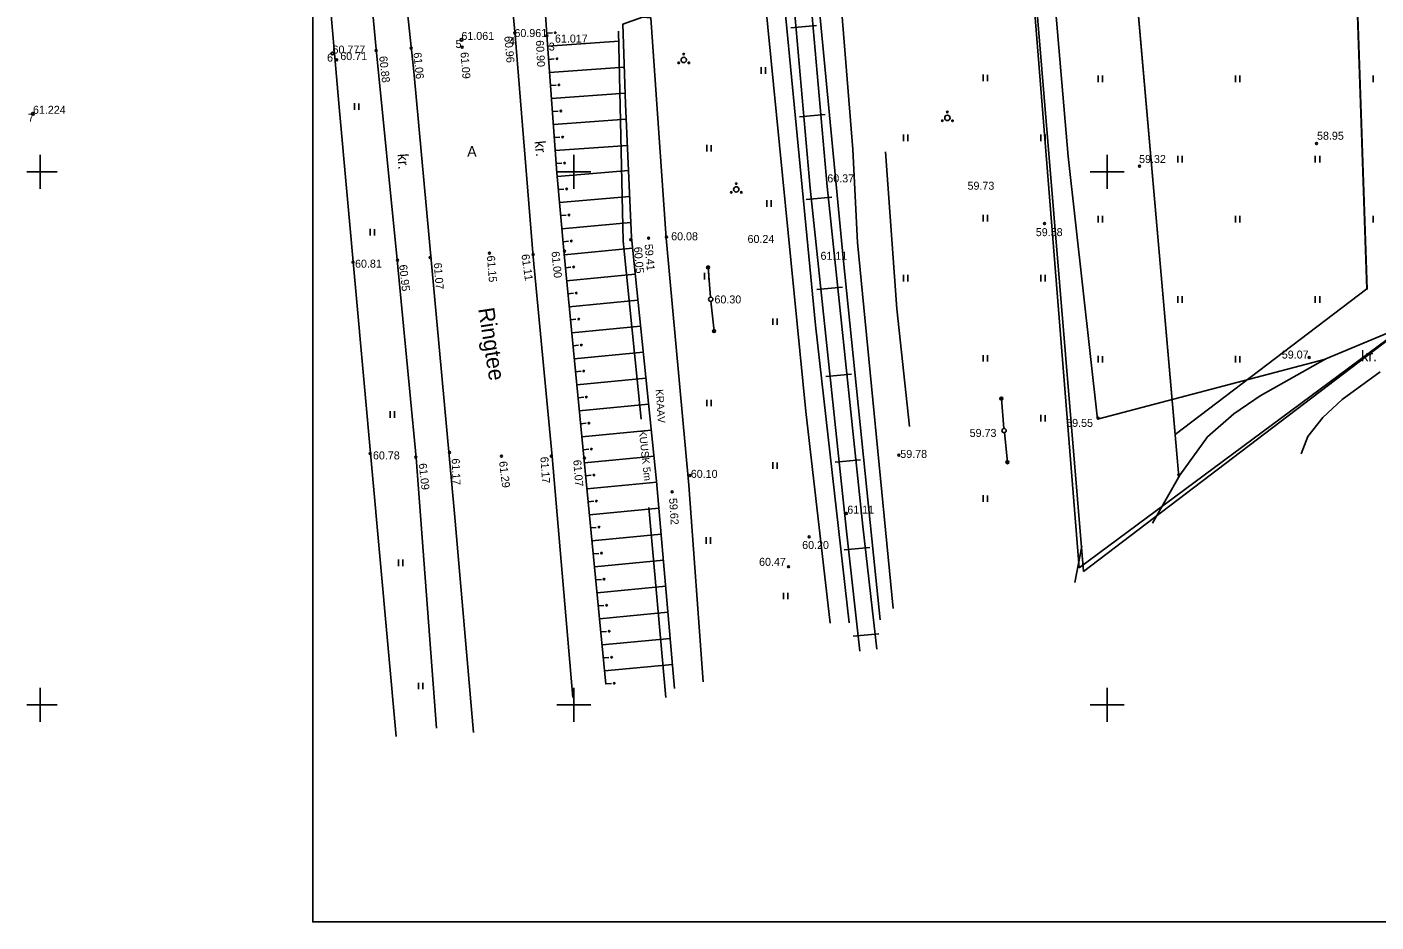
# Model space of a CAD drawing. Extents: x 9156 to 9809, y 2728 to 4000.
# Drawn here: x 9248.8 to 9375.2, y 3329.6 to 3413.6 of the extents above; entities that cross this region are included whole.
import ezdxf

# ---------------------------------------------------------------- set-up
doc = ezdxf.new("R2010")
doc.units = 0
for name, color, linetype in [('Level 1', 7, 'Continuous'), ('Level 11', 7, 'Continuous'), ('Level 54', 7, 'Continuous'), ('Level 58', 7, 'Continuous'), ('Level 6', 7, 'Continuous'), ('Level 63', 7, 'Continuous'), ('Level 7', 7, 'Continuous')]:
    doc.layers.add(name, color=color, linetype=linetype)

# ---------------------------------------------------------------- blocks, each defined once
blk = doc.blocks.new('KKOL')
at = {"layer": 'Level 58'}
for p, q in [((0, 1.59349), (0, -1.5935)), ((-1.5935, 0), (1.59349, 0))]:
    blk.add_line(p, q, dxfattribs=at)

msp = doc.modelspace()

# ---------------------------------------------------------------- linework, layer by layer
at = {"layer": 'Level 1'}
for p, q in [((9347.38, 3362.85), (9317.65, 3734.12)), ((9347.38, 3362.85), (9317.65, 3734.12)), ((9524.24, 3494.13), (9347.38, 3362.85)), ((9524.24, 3494.13), (9347.38, 3362.85)), ((9356.73, 3371.39), (9356.63, 3371.66)), ((9356.63, 3371.66), (9356.73, 3371.53)), ((9356.73, 3371.39), (9356.63, 3371.66)), ((9356.63, 3371.66), (9356.73, 3371.53)), ((9356.73, 3371.39), (9356.63, 3371.66)), ((9356.63, 3371.66), (9356.73, 3371.53)), ((9356.73, 3371.39), (9356.63, 3371.66)), ((9356.63, 3371.66), (9356.73, 3371.53)), ((9356.73, 3371.39), (9356.63, 3371.66)), ((9356.63, 3371.66), (9356.73, 3371.53)), ((9356.73, 3371.39), (9356.63, 3371.66)), ((9356.63, 3371.66), (9356.73, 3371.53)), ((9356.73, 3371.39), (9356.63, 3371.66)), ((9356.63, 3371.66), (9356.73, 3371.53)), ((9356.73, 3371.39), (9356.63, 3371.66)), ((9356.63, 3371.66), (9356.73, 3371.53)), ((9356.89, 3371.7), (9356.73, 3371.39)), ((9356.73, 3371.53), (9356.89, 3371.7)), ((9356.89, 3371.7), (9356.73, 3371.39)), ((9356.73, 3371.53), (9356.89, 3371.7)), ((9356.89, 3371.7), (9356.73, 3371.39)), ((9356.73, 3371.53), (9356.89, 3371.7)), ((9356.89, 3371.7), (9356.73, 3371.39)), ((9356.73, 3371.53), (9356.89, 3371.7)), ((9356.89, 3371.7), (9356.73, 3371.39)), ((9356.73, 3371.53), (9356.89, 3371.7)), ((9356.89, 3371.7), (9356.73, 3371.39)), ((9356.73, 3371.53), (9356.89, 3371.7)), ((9356.89, 3371.7), (9356.73, 3371.39)), ((9356.73, 3371.53), (9356.89, 3371.7)), ((9356.89, 3371.7), (9356.73, 3371.39)), ((9356.73, 3371.53), (9356.89, 3371.7)), ((9347.63, 3364.87), (9346.98, 3361.49)), ((9347.63, 3364.87), (9346.98, 3361.49))]:
    msp.add_line(p, q, dxfattribs=at)
at = {"layer": 'Level 11'}
msp.add_lwpolyline([(9370.59, 3498.94), (9345.6, 3498.32), (9356.38, 3375.35), (9374.34, 3389.03)], close=True, dxfattribs=at)
msp.add_lwpolyline([(9370.59, 3498.94), (9345.6, 3498.32), (9356.38, 3375.35), (9374.34, 3389.03)], close=True, dxfattribs=at)
at = {"layer": 'Level 54'}
for p, q in [((9320.71, 3439.87), (9325.24, 3391.91)), ((9294.51, 3412.82), (9292.27, 3435.4)), ((9283.43, 3424.1), (9285, 3409.41)), ((9346.35, 3401.44), (9344.53, 3422.43)), ((9321.74, 3377.52), (9317.43, 3421.43)), ((9281.48, 3411.48), (9281.03, 3416.19)), ((9322.66, 3385.6), (9319.8, 3415.37)), ((9297.48, 3412.99), (9298.01, 3413.02)), ((9304.2, 3413.18), (9304.64, 3393.5)), ((9320.36, 3413.49), (9322.76, 3413.7)), ((9296.2, 3392.01), (9294.51, 3412.82)), ((9304.22, 3412.24), (9297.57, 3411.76)), ((9283.45, 3391.74), (9281.48, 3411.48)), ((9297.66, 3410.54), (9298.18, 3410.58)), ((9285, 3409.41), (9288.81, 3367.95)), ((9304.73, 3409.82), (9297.74, 3409.32)), ((9317.57, 3409.81), (9317.57, 3409.19)), ((9317.97, 3409.8), (9317.97, 3409.19)), ((9338.37, 3409.11), (9338.37, 3408.49)), ((9338.78, 3409.1), (9338.78, 3408.49)), ((9297.83, 3408.1), (9298.36, 3408.13)), ((9349.15, 3409.02), (9349.15, 3408.4)), ((9349.56, 3409.01), (9349.56, 3408.4)), ((9362.03, 3409.02), (9362.03, 3408.4)), ((9362.44, 3409.01), (9362.44, 3408.4)), ((9374.92, 3409.02), (9374.92, 3408.4)), ((9304.82, 3407.37), (9297.92, 3406.87)), ((9279.46, 3406.42), (9279.46, 3405.8)), ((9279.86, 3406.41), (9279.86, 3405.8)), ((9298.01, 3405.65), (9298.53, 3405.69)), ((9321.16, 3405.14), (9323.56, 3405.36)), ((9304.92, 3404.92), (9298.1, 3404.43)), ((9298.18, 3403.21), (9298.71, 3403.24)), ((9330.9, 3403.49), (9330.9, 3402.87)), ((9331.3, 3403.48), (9331.3, 3402.87)), ((9343.78, 3403.49), (9343.78, 3402.87)), ((9344.18, 3403.48), (9344.18, 3402.87)), ((9250, 3401.59), (9250, 3398.41)), ((9305.03, 3402.47), (9298.27, 3401.98)), ((9312.47, 3402.51), (9312.47, 3401.89)), ((9312.87, 3402.5), (9312.87, 3401.89)), ((9356.63, 3401.49), (9356.63, 3400.87)), ((9357.03, 3401.48), (9357.03, 3400.87)), ((9369.51, 3401.49), (9369.51, 3400.87)), ((9369.92, 3401.48), (9369.92, 3400.87)), ((9250, 3401.25), (9250, 3398.75)), ((9298.36, 3400.76), (9298.88, 3400.8)), ((9300, 3401.25), (9300, 3398.75)), ((9349.08, 3376.81), (9346.35, 3401.44)), ((9350, 3401.25), (9350, 3398.75)), ((9248.75, 3400), (9251.25, 3400)), ((9250, 3400), (9251.59, 3400)), ((9305.13, 3400.13), (9298.45, 3399.54)), ((9298.75, 3400), (9301.25, 3400)), ((9348.75, 3400), (9351.25, 3400)), ((9298.56, 3398.32), (9299.08, 3398.36)), ((9305.24, 3397.68), (9298.67, 3397.1)), ((9318.11, 3397.33), (9318.11, 3396.71)), ((9318.52, 3397.32), (9318.52, 3396.71)), ((9321.8, 3397.38), (9324.2, 3397.6)), ((9298.77, 3395.88), (9299.3, 3395.92)), ((9305.35, 3395.23), (9298.88, 3394.66)), ((9338.37, 3395.96), (9338.37, 3395.34)), ((9338.78, 3395.95), (9338.78, 3395.34)), ((9349.15, 3395.87), (9349.15, 3395.25)), ((9349.56, 3395.86), (9349.56, 3395.25)), ((9362.03, 3395.87), (9362.03, 3395.25)), ((9362.44, 3395.86), (9362.44, 3395.25)), ((9374.92, 3395.87), (9374.92, 3395.25)), ((9280.93, 3394.63), (9280.93, 3394.01)), ((9281.33, 3394.62), (9281.33, 3394.01)), ((9298.99, 3393.44), (9299.51, 3393.48)), ((9305.52, 3392.84), (9299.1, 3392.21)), ((9304.64, 3393.5), (9306.33, 3376.81)), ((9285.24, 3373.17), (9283.45, 3391.74)), ((9297.99, 3373.29), (9296.2, 3392.01)), ((9325.24, 3391.91), (9328.1, 3364.05)), ((9299.22, 3390.99), (9299.74, 3391.05)), ((9305.77, 3390.4), (9299.33, 3389.77)), ((9312.26, 3390.51), (9312.26, 3389.89)), ((9312.82, 3388.24), (9312.59, 3391.03)), ((9312.67, 3390.5), (9312.67, 3389.89)), ((9330.9, 3390.34), (9330.9, 3389.72)), ((9331.3, 3390.33), (9331.3, 3389.72)), ((9343.78, 3390.34), (9343.78, 3389.72)), ((9344.18, 3390.33), (9344.18, 3389.72)), ((9322.79, 3388.96), (9325.19, 3389.18)), ((9386.88, 3389.34), (9370.49, 3382.44)), ((9299.45, 3388.55), (9299.98, 3388.61)), ((9306.02, 3387.96), (9299.57, 3387.34)), ((9312.86, 3387.85), (9313.15, 3385.06)), ((9356.63, 3388.34), (9356.63, 3387.72)), ((9357.03, 3388.33), (9357.03, 3387.72)), ((9369.51, 3388.34), (9369.51, 3387.72)), ((9369.92, 3388.33), (9369.92, 3387.72)), ((9299.69, 3386.12), (9300.21, 3386.17)), ((9306.27, 3385.52), (9299.81, 3384.9)), ((9318.65, 3386.25), (9318.65, 3385.63)), ((9319.06, 3386.24), (9319.06, 3385.63)), ((9325.8, 3357.7), (9322.66, 3385.6)), ((9299.93, 3383.68), (9300.45, 3383.73)), ((9306.52, 3383.09), (9300.05, 3382.46)), ((9338.37, 3382.81), (9338.37, 3382.19)), ((9338.78, 3382.8), (9338.78, 3382.19)), ((9349.15, 3382.72), (9349.15, 3382.1)), ((9349.56, 3382.71), (9349.56, 3382.1)), ((9362.03, 3382.72), (9362.03, 3382.1)), ((9362.44, 3382.71), (9362.44, 3382.1)), ((9300.17, 3381.24), (9300.69, 3381.29)), ((9370.47, 3382.43), (9349.08, 3376.81)), ((9370.49, 3382.44), (9364.33, 3378.97)), ((9306.77, 3380.65), (9300.28, 3380.02)), ((9323.62, 3380.79), (9326.02, 3381.01)), ((9375.6, 3381.22), (9372.04, 3378.63)), ((9300.4, 3378.8), (9300.93, 3378.85)), ((9340.32, 3375.93), (9340.08, 3378.72)), ((9364.33, 3378.97), (9361.87, 3377.28)), ((9282.8, 3377.55), (9282.8, 3376.93)), ((9283.2, 3377.54), (9283.2, 3376.93)), ((9307.02, 3378.21), (9300.52, 3377.58)), ((9312.47, 3378.62), (9312.47, 3378)), ((9312.87, 3378.61), (9312.87, 3378)), ((9324.04, 3357.67), (9321.74, 3377.52)), ((9372.04, 3378.63), (9370.22, 3376.95)), ((9300.64, 3376.36), (9301.16, 3376.41)), ((9343.78, 3377.19), (9343.78, 3376.57)), ((9344.18, 3377.18), (9344.18, 3376.57)), ((9361.87, 3377.28), (9359.4, 3375.14)), ((9370.22, 3376.95), (9368.82, 3375.17)), ((9307.27, 3375.77), (9300.76, 3375.14)), ((9340.36, 3375.53), (9340.65, 3372.75)), ((9359.4, 3375.14), (9356.82, 3371.54)), ((9368.82, 3375.17), (9368.18, 3373.54)), ((9300.88, 3373.92), (9301.4, 3373.97)), ((9287.14, 3347.81), (9285.24, 3373.17)), ((9299.9, 3350.68), (9297.99, 3373.29)), ((9307.53, 3373.33), (9301, 3372.7)), ((9318.65, 3372.75), (9318.65, 3372.13)), ((9319.06, 3372.74), (9319.06, 3372.13)), ((9324.49, 3372.75), (9326.89, 3372.97)), ((9301.11, 3371.48), (9301.64, 3371.53)), ((9356.82, 3371.54), (9354.24, 3367.05)), ((9307.78, 3370.89), (9301.23, 3370.26)), ((9301.35, 3369.04), (9301.87, 3369.09)), ((9338.37, 3369.66), (9338.37, 3369.04)), ((9338.78, 3369.65), (9338.78, 3369.04)), ((9288.81, 3367.95), (9290.59, 3347.42)), ((9307.99, 3368.45), (9301.47, 3367.82)), ((9307.05, 3368.52), (9308.62, 3350.69)), ((9301.59, 3366.6), (9302.11, 3366.65)), ((9308.2, 3366.01), (9301.71, 3365.38)), ((9312.4, 3365.73), (9312.4, 3365.11)), ((9312.81, 3365.72), (9312.81, 3365.11)), ((9283.58, 3363.63), (9283.58, 3363.01)), ((9283.99, 3363.62), (9283.99, 3363.01)), ((9301.83, 3364.16), (9302.35, 3364.21)), ((9308.41, 3363.57), (9301.94, 3362.94)), ((9325.36, 3364.54), (9327.76, 3364.75)), ((9328.1, 3364.05), (9328.72, 3357.98)), ((9302.06, 3361.72), (9302.59, 3361.77)), ((9308.62, 3361.13), (9302.18, 3360.5)), ((9319.67, 3360.52), (9319.67, 3359.9)), ((9320.08, 3360.5), (9320.08, 3359.9)), ((9302.3, 3359.28), (9302.82, 3359.33)), ((9308.83, 3358.68), (9302.42, 3358.06)), ((9302.54, 3356.84), (9303.06, 3356.89)), ((9309.04, 3356.24), (9302.66, 3355.62)), ((9326.2, 3356.43), (9328.59, 3356.65)), ((9302.78, 3354.4), (9303.3, 3354.45)), ((9309.25, 3353.8), (9302.89, 3353.18)), ((9250, 3351.59), (9250, 3348.41)), ((9250, 3351.25), (9250, 3348.75)), ((9285.45, 3352.08), (9285.45, 3351.46)), ((9285.86, 3352.07), (9285.86, 3351.46)), ((9300, 3351.25), (9300, 3348.75)), ((9303.01, 3351.96), (9303.54, 3352.01)), ((9350, 3351.25), (9350, 3348.75)), ((9248.75, 3350), (9251.25, 3350)), ((9250, 3350), (9251.59, 3350)), ((9298.75, 3350), (9301.25, 3350)), ((9348.75, 3350), (9351.25, 3350))]:
    msp.add_line(p, q, dxfattribs=at)
for points in [[(9269.66, 3499.36), (9270.5, 3486.65), (9271, 3479.92), (9272.29, 3467.54), (9275.55, 3434.48), (9278.01, 3406.05), (9283.34, 3347.03)], [(9289.47, 3499.61), (9291.13, 3481.49), (9293.37, 3458.68), (9294.72, 3445.97), (9295.39, 3441.25), (9295.95, 3436.3), (9296.18, 3432.13), (9297.52, 3412.39), (9298.42, 3399.91), (9299.09, 3392.26), (9303.01, 3351.95)], [(9313.56, 3493.85), (9314.49, 3483.91), (9316.62, 3460.38), (9319.31, 3429.93), (9319.91, 3424.01), (9322.16, 3398.47), (9325.52, 3366.57), (9326.81, 3355.03)], [(9315.15, 3494), (9316.08, 3484.06), (9318.21, 3460.52), (9320.9, 3430.08), (9321.51, 3424.16), (9323.75, 3398.63), (9327.11, 3366.75), (9328.4, 3355.21)], [(9324.33, 3425.04), (9326.17, 3402.1), (9326.61, 3393.37), (9329.93, 3359.03)], [(9309.45, 3351.53), (9307.77, 3370.97), (9305.41, 3393.82), (9304.85, 3406.37), (9304.59, 3413.83), (9306.44, 3414.5), (9307.21, 3414.44), (9308.67, 3393.76), (9310.8, 3370.62), (9312.13, 3352.15)], [(9331.47, 3376.1), (9330.28, 3387.15), (9329.23, 3401.86)]]:
    msp.add_lwpolyline(points, dxfattribs=at)
for centre, radius in [((9294.47, 3413.01), 0.0909), ((9297.47, 3412.76), 0.0909), ((9298.26, 3413.03), 0.0683), ((9284.77, 3411.58), 0.0909), ((9289.47, 3412.36), 0.125), ((9289.55, 3411.68), 0.0909), ((9277.39, 3411.08), 0.125), ((9277.78, 3410.49), 0.0909), ((9281.47, 3411.38), 0.0909), ((9298.44, 3410.59), 0.0683), ((9310.31, 3410.48), 0.25), ((9310.31, 3411.03), 0.0707), ((9309.84, 3410.21), 0.0707), ((9310.79, 3410.21), 0.0707), ((9298.61, 3408.14), 0.0683), ((9249.31, 3405.43), 0.125), ((9298.79, 3405.7), 0.0683), ((9335.02, 3405.05), 0.25), ((9335.02, 3405.6), 0.0707), ((9334.55, 3404.78), 0.0707), ((9335.5, 3404.78), 0.0707), ((9298.96, 3403.25), 0.0683), ((9369.63, 3402.64), 0.0909), ((9299.14, 3400.81), 0.0683), ((9353.04, 3400.52), 0.0909), ((9315.23, 3398.89), 0.0707), ((9299.34, 3398.38), 0.0683), ((9314.76, 3398.07), 0.0707), ((9315.23, 3398.34), 0.25), ((9315.71, 3398.07), 0.0707), ((9299.55, 3395.94), 0.0683), ((9344.13, 3395.14), 0.0909), ((9308.69, 3393.88), 0.0909), ((9299.14, 3392.55), 0.0909), ((9299.77, 3393.5), 0.0683), ((9305.34, 3393.63), 0.0909), ((9307.02, 3393.78), 0.0909), ((9279.31, 3391.51), 0.0909), ((9283.49, 3391.71), 0.0909), ((9286.54, 3391.95), 0.0909), ((9292.1, 3392.35), 0.0909), ((9296.19, 3392.25), 0.0909), ((9299.99, 3391.06), 0.0683), ((9312.59, 3391.03), 0.136), ((9312.59, 3391.03), 0.121), ((9312.59, 3391.03), 0.107), ((9312.59, 3391.03), 0.0902), ((9312.59, 3391.03), 0.0749), ((9312.59, 3391.03), 0.0616), ((9312.59, 3391.03), 0.0468), ((9312.59, 3391.03), 0.0343), ((9312.59, 3391.03), 0.0209), ((9312.59, 3391.03), 0.0112), ((9300.23, 3388.62), 0.0683), ((9312.84, 3388.04), 0.2), ((9312.84, 3388.04), 0.2), ((9300.47, 3386.18), 0.0683), ((9313.15, 3385.06), 0.136), ((9313.15, 3385.06), 0.121), ((9313.15, 3385.06), 0.107), ((9313.15, 3385.06), 0.0902), ((9313.15, 3385.06), 0.0749), ((9313.15, 3385.06), 0.0616), ((9313.15, 3385.06), 0.0468), ((9313.15, 3385.06), 0.0343), ((9313.15, 3385.06), 0.0209), ((9313.15, 3385.06), 0.0112), ((9300.71, 3383.74), 0.0683), ((9368.94, 3382.58), 0.0909), ((9300.94, 3381.3), 0.0683), ((9301.18, 3378.86), 0.0683), ((9340.08, 3378.72), 0.136), ((9340.08, 3378.72), 0.121), ((9340.08, 3378.72), 0.107), ((9340.08, 3378.72), 0.0902), ((9340.08, 3378.72), 0.0749), ((9340.08, 3378.72), 0.0616), ((9340.08, 3378.72), 0.0468), ((9340.08, 3378.72), 0.0343), ((9340.08, 3378.72), 0.0209), ((9340.08, 3378.72), 0.0112), ((9301.42, 3376.42), 0.0683), ((9349.15, 3376.9), 0.0909), ((9340.34, 3375.73), 0.2), ((9340.34, 3375.73), 0.2), ((9280.93, 3373.57), 0.0909), ((9288.36, 3373.67), 0.0909), ((9301.66, 3373.99), 0.0683), ((9285.21, 3373.23), 0.0909), ((9293.22, 3373.33), 0.0909), ((9297.9, 3373.33), 0.0909), ((9301, 3373.13), 0.0909), ((9330.48, 3373.43), 0.0909), ((9340.65, 3372.75), 0.136), ((9340.65, 3372.75), 0.121), ((9340.65, 3372.75), 0.107), ((9340.65, 3372.75), 0.0902), ((9340.65, 3372.75), 0.0749), ((9340.65, 3372.75), 0.0616), ((9340.65, 3372.75), 0.0468), ((9340.65, 3372.75), 0.0343), ((9340.65, 3372.75), 0.0209), ((9340.65, 3372.75), 0.0112), ((9301.89, 3371.55), 0.0683), ((9310.89, 3371.5), 0.0909), ((9309.22, 3369.97), 0.0909), ((9302.13, 3369.11), 0.0683), ((9325.56, 3367.95), 0.0909), ((9302.37, 3366.67), 0.0683), ((9322.06, 3365.77), 0.0909), ((9302.6, 3364.23), 0.0683), ((9320.14, 3362.96), 0.0909), ((9302.84, 3361.79), 0.0683), ((9303.08, 3359.35), 0.0683), ((9303.32, 3356.91), 0.0683), ((9303.55, 3354.47), 0.0683), ((9303.79, 3352.03), 0.0683)]:
    msp.add_circle(centre, radius, dxfattribs=at)
at = {"layer": 'Level 6'}
for p, q in [((9306.37, 3945.86), (9356.73, 3371.39)), ((9370.63, 3498.86), (9374.38, 3388.96))]:
    msp.add_line(p, q, dxfattribs=at)
at = {"layer": 'Level 63'}
msp.add_lwpolyline([(9275.53, 3966.8), (9801.62, 3966.8), (9801.62, 3329.64), (9275.53, 3329.64)], close=True, dxfattribs=at)
at = {"layer": 'Level 7'}
for p, q in [((9336.15, 3503.09), (9347.79, 3362.52)), ((9347.79, 3362.52), (9391.88, 3396.1))]:
    msp.add_line(p, q, dxfattribs=at)

# ---------------------------------------------------------------- block references
at = {"layer": 'Level 54'}
for p in [(9300, 3400), (9350, 3400), (9300, 3350), (9350, 3350)]:
    msp.add_blockref('KKOL', p, dxfattribs=at)

# ---------------------------------------------------------------- texts
for s, height, p in [('61.061', 0.75, (9289.47, 3412.36)), ('60.961', 0.75, (9294.44, 3412.63)), ('61.017', 0.75, (9298.24, 3412.11)), ('60.777', 0.75, (9277.39, 3411.08)), ('5', 0.75, (9288.92, 3411.61)), ('4', 0.75, (9293.93, 3411.88)), ('3', 0.75, (9297.66, 3411.36)), ('6', 0.75, (9276.88, 3410.33)), ('60.71', 0.75, (9278.12, 3410.47)), ('7', 0.75, (9248.84, 3404.68)), ('61.224', 0.75, (9249.31, 3405.43)), ('58.95', 0.75, (9369.67, 3403)), ('A', 1, (9290.01, 3401.4)), ('59.32', 0.75, (9352.99, 3400.82)), ('60.37', 0.75, (9323.77, 3399)), ('59.73', 0.75, (9336.91, 3398.31)), ('60.08', 0.75, (9309.13, 3393.57)), ('60.24', 0.75, (9316.29, 3393.32)), ('59.58', 0.75, (9343.31, 3393.96)), ('60.81', 0.75, (9279.5, 3391)), ('61.11', 0.75, (9323.13, 3391.74)), ('60.30', 0.75, (9313.19, 3387.65)), ('59.07', 0.75, (9366.37, 3382.48)), ('kr.', 1, (9373.81, 3382.22)), ('59.55', 0.75, (9346.16, 3376.07)), ('59.73', 0.75, (9337.11, 3375.13)), ('60.78', 0.75, (9281.18, 3373.02)), ('59.78', 0.75, (9330.61, 3373.16)), ('60.10', 0.75, (9310.97, 3371.29)), ('61.11', 0.75, (9325.64, 3367.93)), ('60.20', 0.75, (9321.41, 3364.62)), ('60.47', 0.75, (9317.37, 3363.04))]:
    msp.add_text(s, height=height, dxfattribs=at).set_placement(p)
for s, height, rotation, p in [('60.96', 0.75, 275.1793, (9293.48, 3412.69)), ('60.90', 0.75, 273.1705, (9296.44, 3412.31)), ('60.88', 0.75, 276.4645, (9281.76, 3410.81)), ('61.06', 0.75, 275.7988, (9284.97, 3411.16)), ('61.09', 0.75, 274.7499, (9289.38, 3411.19)), ('kr.', 1, 275.6244, (9296.33, 3402.85)), ('kr.', 1, 273.6808, (9283.48, 3401.66)), ('60.05', 0.75, 274.4285, (9305.64, 3392.93)), ('59.41', 0.75, 275.1795, (9306.64, 3393.19)), ('61.07', 0.75, 274.386, (9286.88, 3391.44)), ('61.15', 0.75, 274.5008, (9291.86, 3392.11)), ('61.11', 0.75, 278.1069, (9295.09, 3392.22)), ('61.00', 0.75, 275.6941, (9297.91, 3392.5)), ('60.95', 0.75, 276.3688, (9283.63, 3391.25)), ('Ringtee', 1.5, 278.818, (9291.04, 3387.15)), ('KRAAV', 0.7, 273.7045, (9307.68, 3379.58)), ('KUUSK 5m', 0.7, 276.0443, (9306.1, 3375.74)), ('61.09', 0.75, 276.1977, (9285.47, 3372.62)), ('61.17', 0.75, 271.8035, (9288.56, 3373.11)), ('61.29', 0.75, 276.9611, (9293, 3372.81)), ('61.17', 0.75, 273.8891, (9296.87, 3373.25)), ('61.07', 0.75, 274.6221, (9299.95, 3372.95)), ('59.62', 0.75, 273.9339, (9308.93, 3369.37))]:
    msp.add_text(s, height=height, rotation=rotation, dxfattribs=at).set_placement(p)

doc.saveas('drawing.dxf')
